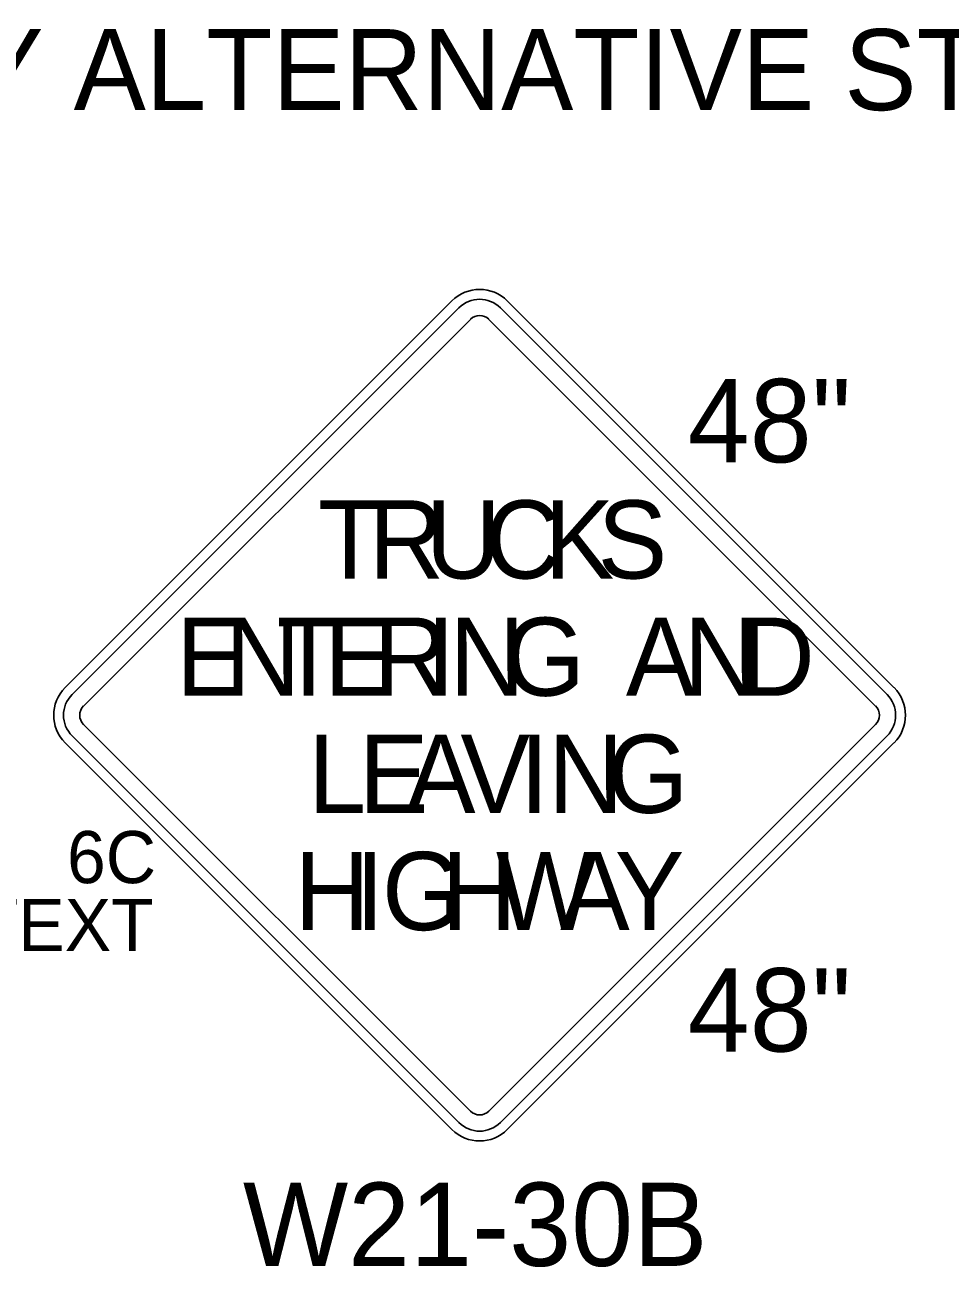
# Model space of a CAD drawing. Extents: x 99999 to 100116, y 99995 to 100013.
# Drawn here: x 100033.098 to 100033.897, y 100001.176 to 100002.249 of the extents above; entities that cross this region are included whole.
import ezdxf

# ---------------------------------------------------------------- set-up
doc = ezdxf.new("R2010")
doc.units = 0
doc.layers.add('SH_GI_GeneralNotesBodyText', color=7, linetype='Continuous')
doc.layers.add('TR_SN_ConstructionSigns', color=7, linetype='Continuous')

msp = doc.modelspace()

# ---------------------------------------------------------------- linework, layer by layer
at = {"layer": 'TR_SN_ConstructionSigns'}
for p, q in [((100033.4669, 100002.0107), (100033.1328, 100001.6766)), ((100033.8487, 100001.6766), (100033.5146, 100002.0107)), ((100033.4729, 100002.0048), (100033.1387, 100001.6707)), ((100033.8428, 100001.6707), (100033.5087, 100002.0048)), ((100033.1487, 100001.6607), (100033.4828, 100001.9948)), ((100033.4987, 100001.9948), (100033.8328, 100001.6607)), ((100033.4828, 100001.3107), (100033.1487, 100001.6448)), ((100033.8328, 100001.6448), (100033.4987, 100001.3107)), ((100033.1387, 100001.6349), (100033.4729, 100001.3008)), ((100033.5087, 100001.3008), (100033.8428, 100001.6349)), ((100033.1328, 100001.6289), (100033.4669, 100001.2948)), ((100033.5146, 100001.2948), (100033.8487, 100001.6289))]:
    msp.add_line(p, q, dxfattribs=at)
for centre, radius, start, end in [((100033.4908, 100001.9869), 0.0338, 45, 135), ((100033.4908, 100001.9869), 0.0253, 45, 135), ((100033.4908, 100001.9869), 0.0113, 45, 135), ((100033.1566, 100001.6528), 0.0338, 135, 225), ((100033.8249, 100001.6528), 0.0338, 315, 45), ((100033.1566, 100001.6528), 0.0253, 135, 225), ((100033.8249, 100001.6528), 0.0253, 315, 45), ((100033.1566, 100001.6528), 0.0113, 135, 225), ((100033.8249, 100001.6528), 0.0113, 315, 45), ((100033.4908, 100001.3187), 0.0253, 225, 315), ((100033.4908, 100001.3187), 0.0113, 225, 315), ((100033.4908, 100001.3187), 0.0338, 225, 315)]:
    msp.add_arc(centre, radius, start, end, dxfattribs=at)

# ---------------------------------------------------------------- texts
at = {"layer": 'SH_GI_GeneralNotesBodyText'}
msp.add_text('(C) ENGINEER TO ACCEPT ANY ALTERNATIVE STRATEGIES.', height=0.07, rotation=360, dxfattribs=at).set_placement((100031.689, 100002.1756))
at = {"layer": 'TR_SN_ConstructionSigns'}
for s, p in [('48"', (100033.6706, 100001.8713)), ('48"', (100033.6706, 100001.3622)), ('W21-30B', (100033.2863, 100001.1769))]:
    msp.add_text(s, height=0.072, rotation=360, dxfattribs=at).set_placement(p)
for s, height, p in [('T', 0.0675, (100033.351, 100001.7709)), ('R', 0.0675, (100033.3949, 100001.7709)), ('U', 0.0675, (100033.4442, 100001.7709)), ('C', 0.0675, (100033.4955, 100001.7709)), ('K', 0.0675, (100033.5468, 100001.7709)), ('S', 0.0675, (100033.5927, 100001.7709)), ('E', 0.0675, (100033.2286, 100001.6696)), ('N', 0.0675, (100033.271, 100001.6696)), ('T', 0.0675, (100033.3154, 100001.6696)), ('E', 0.0675, (100033.3565, 100001.6696)), ('R', 0.0675, (100033.3989, 100001.6696)), ('I', 0.0675, (100033.4448, 100001.6696)), ('N', 0.0675, (100033.4646, 100001.6696)), ('G', 0.0675, (100033.5118, 100001.6696)), ('A', 0.0675, (100033.6171, 100001.6696)), ('N', 0.0675, (100033.667, 100001.6696)), ('D', 0.0675, (100033.7152, 100001.6696)), ('L', 0.0675, (100033.3426, 100001.5684)), ('E', 0.0675, (100033.3865, 100001.5684)), ('A', 0.0675, (100033.427, 100001.5684)), ('V', 0.0675, (100033.4742, 100001.5684)), ('I', 0.0675, (100033.5255, 100001.5684)), ('N', 0.0675, (100033.5498, 100001.5684)), ('G', 0.0675, (100033.6011, 100001.5684)), ('6C', 0.045, (100033.1343, 100001.5077)), ('H', 0.0675, (100033.3308, 100001.4671)), ('I', 0.0675, (100033.3834, 100001.4671)), ('G', 0.0675, (100033.4064, 100001.4671)), ('H', 0.0675, (100033.4577, 100001.4671)), ('W', 0.0675, (100033.5049, 100001.4671)), ('A', 0.0675, (100033.5603, 100001.4671)), ('Y', 0.0675, (100033.6075, 100001.4671)), ('TEXT', 0.045, (100033.0554, 100001.4491))]:
    msp.add_text(s, height=height, dxfattribs=at).set_placement(p)

doc.saveas('drawing.dxf')
